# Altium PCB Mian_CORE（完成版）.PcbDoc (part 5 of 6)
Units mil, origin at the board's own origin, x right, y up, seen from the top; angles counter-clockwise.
Board outline 2755.91 x 1771.65 mil, 4 copper layers (TOP, GND02, PWR03, BOTTOM); 61 components, 130 nets, 4907 pads, 497 vias.
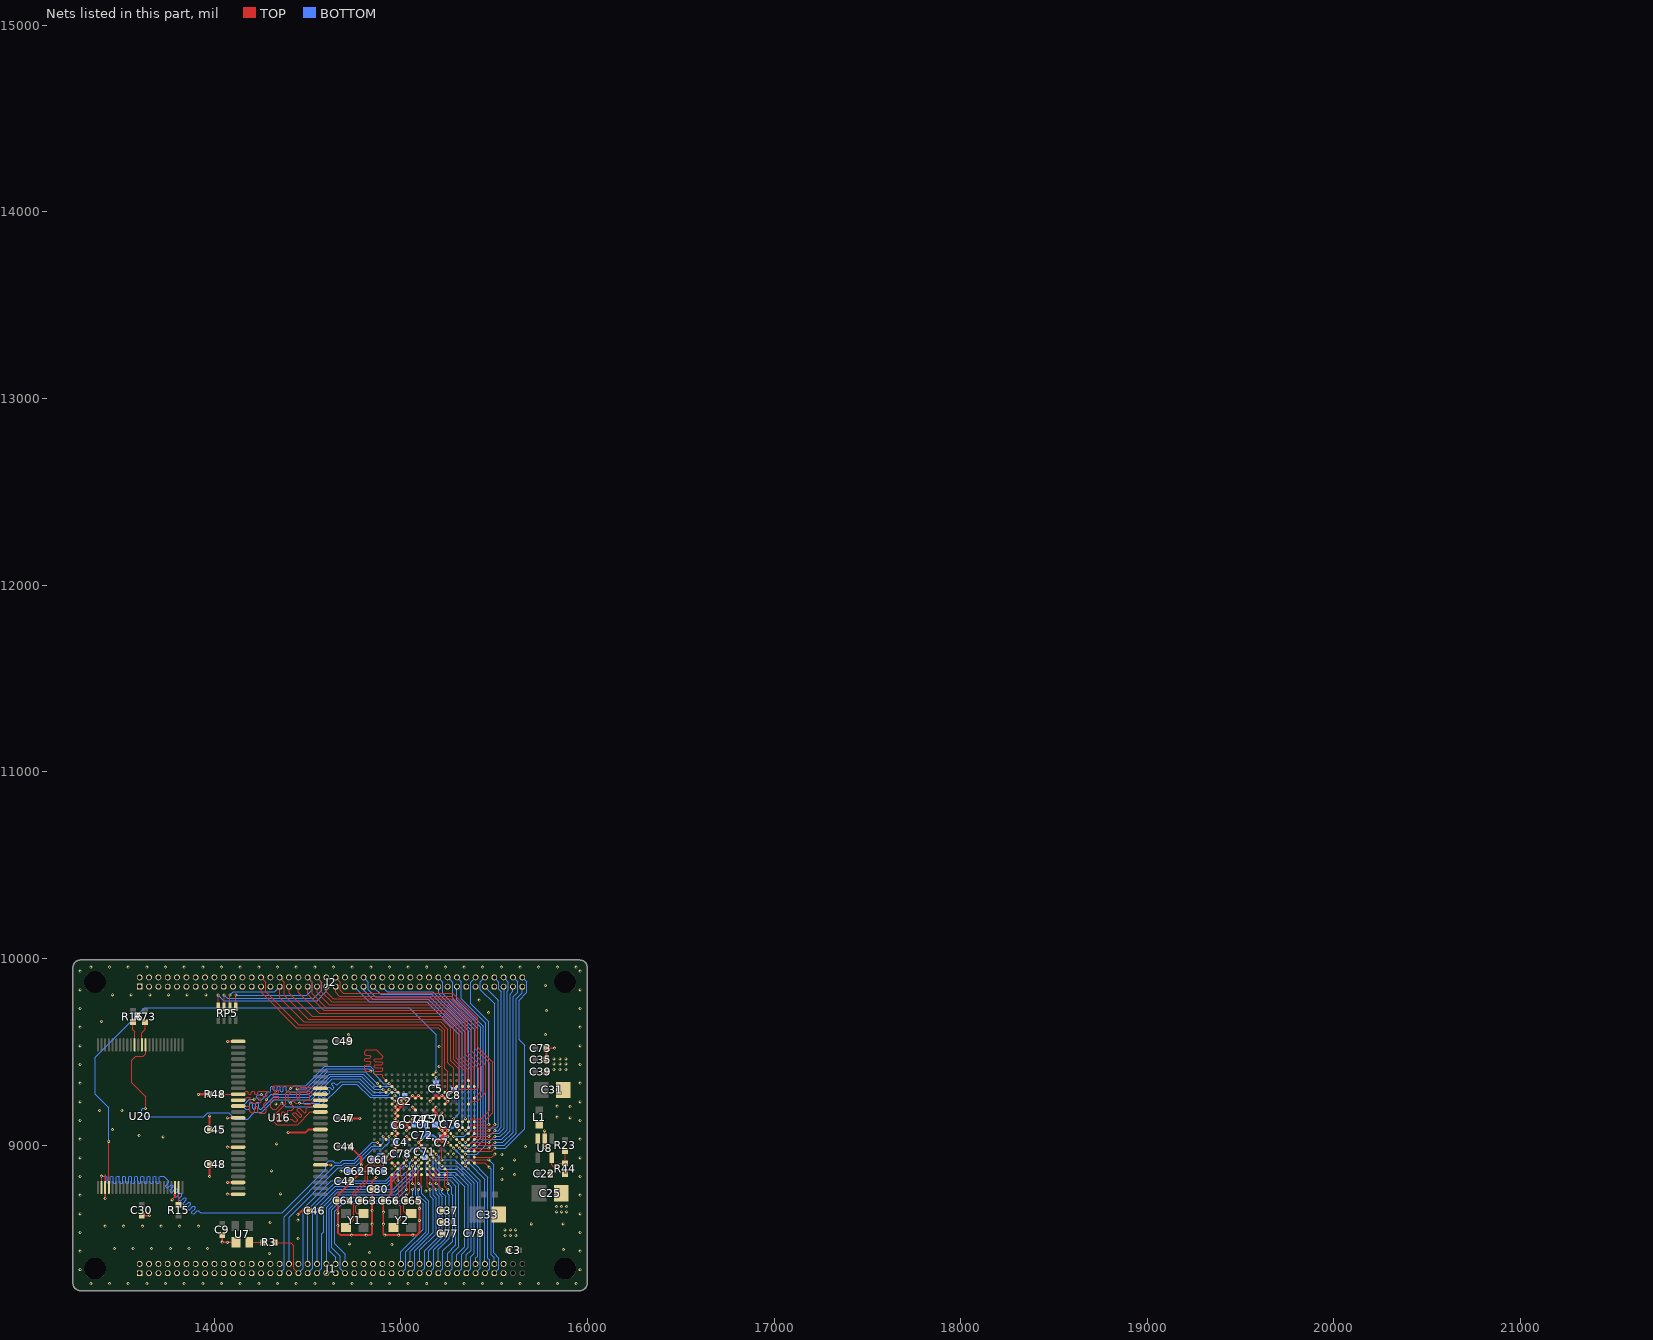
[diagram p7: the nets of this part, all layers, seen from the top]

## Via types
v1: diameter 16, hole 8, TOP to BOTTOM, tented both sides, 497 vias

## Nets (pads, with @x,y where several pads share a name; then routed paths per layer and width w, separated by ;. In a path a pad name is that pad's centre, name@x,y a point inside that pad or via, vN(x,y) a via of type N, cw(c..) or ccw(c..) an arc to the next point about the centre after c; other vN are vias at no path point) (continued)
GND: C2.2 C3.2 C4.2 C5.2 C6.2 C7.2 C8.2 C9.2 C22.1 C25.2 C30.2 C31.2 C33.2 C35.1 C37.1 C39.1 C42.2 C44.2 C45.2 C46.2 C47.2 C48.2 C49.2 C61.2 C62.2 C63.2 C64.2 C65.2 C66.2 C70.2 C71.2 C72.2 C73.2 C74.2 C75.2 C76.2 C77.2 C78.2 C79.2 C80.2 C81.2 J1.1 J1.2 J1.3 J1.4 J1.5 J1.6 J1.7 J1.8 J1.9 J1.10 J1.11 J1.12 J1.13 J1.14 J1.15 J1.16 J1.17 J1.18 J1.19 J1.20 J1.21 J1.22 J1.23 J1.24 J1.25 J1.26 J1.27 J1.28 J1.29 J1.30 J1.32 J1.33 J1.36 J1.41 J1.43 J1.47 J1.48 J1.49 J1.50 J1.51 J1.52 J1.53 J1.54 J1.55 J1.56 J1.79 J1.80 J2.1 J2.2 J2.3 J2.4 J2.5 J2.6 J2.7 J2.8 J2.9 J2.10 J2.11 J2.12 J2.13 J2.14 J2.15 J2.16 J2.17 J2.18 J2.19 J2.20 J2.21 J2.22 J2.23 J2.24 J2.25 J2.26 J2.29 J2.30 J2.34 J2.36 J2.42 J2.45 J2.46 J2.48 J2.52 J2.54 J2.55 J2.56 J2.57 J2.58 J2.59 J2.60 J2.61 J2.62 J2.63 J2.64 J2.67 J2.71 J2.72 J2.73 J2.77 R44.2 R48.1 U1.F5 U1.F6 U1.F10 U1.F11 U1.F12 U1.G5 U1.G8 U1.G10 U1.G12 U1.H5 U1.H7 U1.H12 U1.K5 U1.K12 U1.K13 U1.L5 U1.L7 U1.L14 U1.M5 U1.M9 U1.M10 U1.M12 U1.N5 U1.N6 U1.P6 U1.P7 U1.P8 U1.P9 U1.P10 U1.P11 U1.P13 U1.P14 U1.P18 U1.R16 U1.R18 U1.T15 U7.1 U8.2 U16.6 U16.12 U16.28 U16.41 U16.46 U16.52 U16.54 U20.27 U20.46 | length 5536.5
  TOP w10: v1(13415.99,8714.01) U20.27@13415.99,8773.11 13415.99,8841 ; C30.2@13612,8621.16 v1(13653.84,8621.16) ; v1(13774,8706) 13790.01,8722.01 U20.46@13790.01,8773.11 ; v1(13975.08,8831.08) C48.2@13975.08,8896 ; C45.2@13975.08,9083 v1(13975.08,9155.92) ; C9.2@14043,8517.16 v1(14043,8480) 14044,8479 U7.1@14117.13,8479 ; v1(14072.45,8736.55) U16.54@14128.53,8736.55 ; v1(14072.45,8799.54) U16.52@14128.53,8799.54 ; v1(14072.45,8988.52) U16.46@14128.53,8988.52 ; v1(14072.45,9146) U16.41@14128.53,9146 ; v1(14072.45,9555.45) U16.28@14128.53,9555.45 ; v1(14396,9068) 14489.99,9068 14505,9083.01 U16.12@14569.47,9083.01 ; v1(14448,8627) 14469,8648 C46.2@14510.16,8648 ; U16.6@14569.47,8894.03 v1(14625.55,8894.03) ; 14682.58,8751.58 14698,8767 ; C49.2@14720.92,9555 v1(14720.92,9591.48) ; C47.2@14725.84,9143 v1(14781,9143) ; v1(14788,8892) 14788,8857 14698,8767 ; v1(14867.56,8827) 14846.16,8805.6 C80.2@14846.16,8764 14846,8763.84 C63.2@14846,8701 v1(14846,8648) v1(14846,8576) 14846,8525 14838,8517 v1(14814,8517) v1(14736,8517) 14677,8517 14663.16,8530.84 v1(14663.16,8568) v1(14663.16,8636) C64.2@14663.16,8701 14663.16,8732.16 14698,8767 ; 14949.16,8773 14949.16,8741 C66.2@14909.16,8701 14906,8697.84 v1(14906,8641) v1(14906,8576) 14906,8525 v1(14914,8517) v1(14989,8517) v1(15064,8517) 15085,8517 15100,8532 v1(15100,8596) v1(15100,8659) 15100,8693 C65.2@15092,8701 ; U1.P18@14984.27,8841.28 v1(14984.27,8810.58) v1@14984.38,8810.47 ; v1(15771,8988) U8.2@15771,9034.18 v1(15771,9076) ; C35.1@15779.84,9458 15780.84,9459 C73.2@15780.84,9519 v1(15824,9519)
  TOP w12: v1(13915,9272) R48.1@13975.08,9272 ; C44.2@14728.92,8991 14788,8931.92 v1(14788,8892) ; v1(14905.53,8951.52) U1.T15@14921.28,8935.77 ; 14949.16,8773 14949.16,8837.67 U1.R18@14952.77,8841.28 ; U1.R16@14952.77,8904.28 v1(14968.52,8888.53) ; v1(14968.52,9046.01) U1.P11@14984.27,9061.76 v1(14968.52,9077.5) U1.P10@14984.27,9093.25 14968.52,9109 U1.P9@14984.27,9124.75 v1(14968.52,9140.5) U1.P8@14984.27,9156.24 v1(14968.52,9171.99) U1.P7@14984.27,9187.74 ; U1.P14@14984.27,8967.27 v1(14968.52,8983.02) U1.P13@14984.27,8998.76 ; v1(15031.51,9046.01) U1.M12@15047.26,9030.26 ; v1(15031.51,9077.5) U1.M10@15047.26,9093.25 15031.51,9109 U1.M9@15047.26,9124.75 v1(15063.01,9140.5) ; v1(15063.01,9203.49) U1.L7@15078.76,9187.74 ; U1.L14@15078.76,8967.27 v1(15094.5,8983.02) U1.K13@15110.25,8998.76 v1(15094.5,9014.51) U1.K12@15110.25,9030.26 ; U1.K5@15110.25,9250.73 v1(15094.5,9266.48) U1.L5@15078.76,9250.73 v1(15063.01,9266.48) U1.M5@15047.26,9250.73 v1(15031.51,9234.98) ; v1(15157.5,9234.98) U1.H5@15173.24,9250.73 15188.99,9266.48 U1.G5@15204.74,9250.73 v1(15220.49,9266.48) U1.F5@15236.24,9250.73 ; U1.H12@15173.24,9030.26 v1(15188.99,9014.51) U1.G12@15204.74,9030.26 ; v1(15188.99,9203.49) U1.H7@15173.24,9187.74 15188.99,9171.99 U1.G8@15204.74,9156.24 v1(15220.49,9171.99) ; U1.G10@15204.74,9093.25 v1(15220.49,9077.5) ; U1.F6@15236.24,9219.24 v1(15251.98,9234.98) U1.F5@15236.24,9250.73 ; v1(15251.98,9014.51) U1.F12@15236.24,9030.26 ; v1(15251.98,9266.48) U1.F5@15236.24,9250.73 ; U1.P7@14984.27,9187.74 15000.02,9203.49 ; U1.P7@14984.27,9187.74 v1(14968.52,9203.49) U1.P6@14984.27,9219.24 ; U1.P6@14984.27,9219.24 15000.02,9203.49 ; U1.P6@14984.27,9219.24 v1(15000.02,9234.98) ; 15000.02,9203.49 U1.N6@15015.76,9219.24 ; v1(15000.02,9234.98) U1.N5@15015.76,9250.73 v1(15031.51,9234.98) ; v1(15000.02,9234.98) U1.N6@15015.76,9219.24 ; U1.N6@15015.76,9219.24 v1(15031.51,9234.98) ; U1.G12@15204.74,9030.26 15220.49,9014.51 U1.F12@15236.24,9030.26 ; U1.G12@15204.74,9030.26 15220.49,9046.01 ; 15220.49,9046.01 U1.F12@15236.24,9030.26 ; 15220.49,9046.01 U1.F11@15236.24,9061.76 ; v1(15220.49,9077.5) U1.F11@15236.24,9061.76 ; v1(15220.49,9077.5) U1.F10@15236.24,9093.25 v1(15251.98,9077.5) U1.F11@15236.24,9061.76 ; U1.F12@15236.24,9030.26 v1(15251.98,9046.01) U1.F11@15236.24,9061.76
  BOTTOM w8: v1(15094.5,8983.02) 15122,8955.52
  BOTTOM w10: v1(14679,8860) C62.2@14722.16,8860 ; C61.2@14848.16,8921 14878.68,8951.52 v1(14905.53,8951.52) ; v1(14968.52,9046.01) 14970.16,9044.37 C4.2@14970.16,9015 ; v1(15000.02,9234.98) 15000.02,9243.86 C2.2@15021,9264.84 ; C78.2@15030.84,8953 15060.86,8983.02 v1(15094.5,8983.02) ; v1(15063.01,9140.5) 15063.01,9120.15 C74.2@15074,9109.16 C75.2@15128,9109.16 15133.84,9103.31 15133.84,9052 15175,9052 15188.99,9038.01 v1(15188.99,9014.51) ; C70.2@15183,9110.16 15187.83,9110.16 v1(15220.49,9077.5) ; C5.2@15188,9331 15188.99,9331.99 v1(15188.99,9360.97) ; v1(15251.98,9077.5) 15266.48,9092 15278.84,9092 C76.2@15297.84,9111
  BOTTOM w12: C6.2@14960.08,9106 14960.08,9085.94 v1(14968.52,9077.5) ; v1(15094.5,9014.51) 15096.35,9014.51 C72.2@15133.84,9052 ; 15122,8955.52 15122,8940.16 C71.2@15128,8934.16 ; C7.2@15220.49,9042.86 15223.64,9046.01 v1(15251.98,9046.01) ; v1(15251.98,9266.48) 15281.35,9295.84 C8.2@15285,9295.84
  other v1: 13339,8258 13439,8258 13539,8258 13639,8258 13739,8258 13839,8258 13939,8258 14039,8258 14139,8258 14239,8258 14339,8258 14439,8258 14539,8258 14639,8258 14739,8258 14839,8258 14939,8258 15039,8258 15139,8258 15239,8258 15339,8258 15439,8258 15539,8258 15639,8258 15739,8258 15839,8258 15939,8258 13281,8331.75 15960.91,8331.75 14296,8419 14833,8424 13281,8431.75 15960.91,8431.75 15871,8440 13465,8445 13565,8445 13665,8445 13765,8445 13865,8445 13965,8445 14952,8467 14724,8471 14071,8479 14450,8498 15559,8516 15587.5,8516 15616,8516 13281,8531.75 15960.91,8531.75 15558,8545 15586.5,8545 15615,8545 13415,8566 13515,8566 13615,8566 13715,8566 13815,8566 13915,8566 15699,8577 15870,8577 14300,8585 14449,8598 13281,8631.75 15960.91,8631.75 15835,8642 15861.5,8642 15888,8642 15835,8670 15861.5,8670 15888,8670 13281,8731.75 15960.91,8731.75 14356,8738 15134,8753 15541,8816 13281,8831.75 15960.91,8831.75 15610,8842 14307,8862 15541,8875 15609,8921 13281,8931.75 15960.91,8931.75 15541,8950 15251.98,8951.52 15283.48,8951.52 15668,8992 14334,9006 13281,9031.75 15960.91,9031.75 13726,9044 13598,9051 13454,9082 13281,9131.75 15960.91,9131.75 15907,9145 15838,9150 13386,9186 13505,9186 15907,9206 15838,9208 14330,9221 13281,9231.75 15960.91,9231.75 13281,9331.75 15960.91,9331.75 15820,9406 15852,9406 15884,9406 15205,9421 13281,9431.75 15960.91,9431.75 15820,9435 15852,9435 15884,9435 15820,9462 15852,9462 15884,9462 15205,9527 13281,9531.75 15960.91,9531.75 15775,9592 13281,9631.75 15960.91,9631.75 13397,9663 15471,9709 15780,9720 13281,9731.75 15960.91,9731.75 15420,9776 13455,9805 13555,9805 13655,9805 13755,9805 13855,9805 13955,9805 13281,9831.75 15960.91,9831.75 15775,9855 13281,9931.75 15960.91,9931.75 13339,9953.65 13439,9953.65 13539,9953.65 13639,9953.65 13739,9953.65 13839,9953.65 13939,9953.65 14039,9953.65 14139,9953.65 14239,9953.65 14339,9953.65 14439,9953.65 14539,9953.65 14639,9953.65 14739,9953.65 14839,9953.65 14939,9953.65 15039,9953.65 15139,9953.65 15239,9953.65 15339,9953.65 15439,9953.65 15539,9953.65 15639,9953.65 15739,9953.65 15839,9953.65 15939,9953.65
GPI_00: J1.73 U1.C16 | length 641.8
  TOP w5.5: U1.C16@15330.72,8904.28 v1(15346.47,8888.53)
  BOTTOM w5.5: v1(15346.47,8888.53) 15427,8808 15427,8339.16 J1.73@15400.95,8313.11
GPI_02: J2.70 U1.C14 | length 1114.6
  TOP w5.5: U1.C14@15330.72,8967.27 v1(15346.47,8951.52)
  BOTTOM w5.5: J2.70@15300.95,9898.54 15324,9875.5 15324,9784 15456,9652 15456,9000 15407.52,8951.52 v1(15346.47,8951.52)
GPI_03: J2.28 U1.F4 | length 1479
  TOP w5.5: J2.28@14250.95,9898.54 14276,9873.5 14276,9822 14453.58,9644.42 15207.27,9644.42 15236.42,9615.27 15236.42,9409.58 15252,9394 15252,9297.99 U1.F4@15236.24,9282.23
GPI_04: J1.76 U1.E13 | length 718.7
  TOP w5.5: U1.E13@15267.73,8998.76 v1(15283.48,8983.02)
  BOTTOM w5.5: v1(15283.48,8983.02) 15323,8943.5 15323,8921.02 15339.75,8904.28 15363.72,8904.28 15450.95,8817.05 J1.76@15450.95,8370.05
GPI_05: J1.38 U1.N16 | length 940.8
  TOP w5.5: U1.N16@15015.76,8904.28 v1(15031.51,8888.53)
  BOTTOM w5.5: J1.38@14500.95,8363.11 14500.95,8653.94 14642.01,8795 14924,8795 15017.53,8888.53 v1(15031.51,8888.53)
GPI_07: J2.69 U1.D13 | length 1063.1
  TOP w5.5: U1.D13@15299.23,8998.76 v1(15314.98,8983.02)
  BOTTOM w5.5: J2.69@15300.95,9848.54 15300.95,9779.05 15443,9637 15443,9025 15385.27,8967.27 15330.72,8967.27 v1(15314.98,8983.02)
GPI_08: J1.77 U1.B16 | length 747.9
  TOP w5.5: U1.B16@15362.22,8904.28 15377.97,8920.02 v1(15472.46,8920.02)
  BOTTOM w5.5: v1(15472.46,8920.02) 15498,8894.48 15498,8422 15526,8394 15526,8338.16 J1.77@15506.84,8319
GPI_16: J1.59 U1.J18 | length 591.5
  TOP w5.5: U1.J18@15141.75,8841.28 15141.75,8778.29 v1(15157.5,8762.54)
  BOTTOM w5.5: J1.59@15050.95,8313.11 15075,8337.16 15075,8434 15172.75,8531.75 15172.75,8709.25 15157.5,8724.5 v1(15157.5,8762.54)
GPI_22: J1.74 U1.G13 | length 765.4
  TOP w5.5: U1.G13@15204.74,8998.76 15220.49,8983.02 v1(15220.49,8920.02)
  BOTTOM w5.5: v1(15220.49,8920.02) 15288.98,8920.02 15411,8798 15411,8405 15400.95,8394.95 J1.74@15400.95,8363.11
GPIO_00: J2.80 U1.A12 | length 1027.2
  TOP w5.5: U1.A12@15393.72,9030.26 15488.21,9030.26 v1(15503.95,9046.01)
  BOTTOM w5.5: v1(15503.95,9046.01) 15534.18,9046.01 15570.5,9082.33 15570.5,9823.5 15576,9829 15576,9873.5 J2.80@15550.95,9898.54
GPIO_01: J2.78 U1.A11 | length 978.1
  TOP w5.5: U1.A11@15393.72,9061.76 15488.21,9061.76 v1(15503.95,9077.5)
  BOTTOM w5.5: J2.78@15500.95,9898.54 15526,9873.5 15526,9834 15539,9821 15539,9095.37 15521.13,9077.5 v1(15503.95,9077.5)
GPO_00: J2.33 U1.C3 | length 1456.7
  TOP w5.5: J2.33@14400.95,9848.54 14400.95,9814.05 14524.33,9690.67 15226.43,9690.67 15282.67,9634.43 15282.67,9586 ; 15282.67,9474 15282.67,9586 ; U1.C3@15330.72,9313.72 15347,9330 15347,9394 15282.67,9458.33 15282.67,9586
GPO_01: J2.39 U1.D4 | length 1400.1
  TOP w5.5: J2.39@14550.95,9848.54 14550.95,9817.05 14615.67,9752.33 15251.97,9752.33 15344.33,9659.97 15344.33,9638.41 15344.33,9486.19 15418,9412.53 15418,9311 15405,9298 15315,9298 U1.D4@15299.23,9282.23
GPO_02: J2.83 U1.B14 | length 1087.9
  TOP w5.5: U1.B14@15362.22,8967.27 15377.97,8983.02 v1(15472.46,8983.02)
  BOTTOM w5.5: v1(15472.46,8983.02) 15488.46,8999.02 15553.64,8999.02 15617.49,9062.86 15617.49,9783.49 15650.95,9816.95 J2.83@15650.95,9842.05
GPO_03: J2.66 U1.D12 | length 1084.8
  TOP w5.5: U1.D12@15299.23,9030.26 v1(15314.98,9014.51)
  BOTTOM w5.5: J2.66@15200.95,9898.54 15226,9873.5 15226,9810 15412,9624 15412,9047 15363.76,8998.76 15330.72,8998.76 v1(15314.98,9014.51)
GPO_05: J2.37 U1.B3 | length 1288.6
  TOP w5.5: J2.37@14500.95,9848.54 14500.95,9807.05 14586.5,9721.5 15239.2,9721.5 15313.5,9647.2 15313.5,9470.5 15380,9404 15380,9331.5 U1.B3@15362.22,9313.72
GPO_06: J1.78 U1.A16 | length 619
  TOP w5.5: U1.A16@15393.72,8904.28 15450.72,8904.28 v1(15473,8882)
  BOTTOM w5.5: v1(15473,8882) 15485,8870 15485,8411 15500.95,8395.05 J1.78@15500.95,8363.11
GPO_07: U1.A15 | length 116.8
  TOP w5.5: U1.A15@15393.72,8935.77 15488.21,8935.77 v1(15503.95,8951.52)
GPO_08: J2.68 U1.C13 | length 1061.3
  TOP w5.5: U1.C13@15330.72,8998.76 v1(15346.47,8983.02)
  BOTTOM w5.5: J2.68@15250.95,9898.54 15277,9872.5 15277,9782 15429,9630 15429,9039 15373.02,8983.02 v1(15346.47,8983.02)
GPO_09: J2.65 U1.C12 | length 959
  TOP w5.5: U1.C12@15330.72,9030.26 v1(15346.47,9014.51)
  BOTTOM w5.5: J2.65@15204,9852 15204,9810 15395,9619 15395,9063.04 v1(15346.47,9014.51)
GPO_10: J2.53 U1.E11 | length 1237.9
  TOP w5.5: U1.E11@15267.73,9061.76 v1(15283.48,9046.01)
  BOTTOM w5.5: J2.53@14900.95,9848.54 14927.5,9822 15171,9822 15378,9615 15378,9083 15341.01,9046.01 v1(15283.48,9046.01)
GPO_12: J2.79 U1.B12 | length 977.6
  TOP w5.5: U1.B12@15362.22,9030.26 15377.97,9046.01 v1(15472.46,9046.01)
  BOTTOM w5.5: v1(15472.46,9046.01) 15488.46,9062.01 15527.55,9062.01 15554.5,9088.95 15554.5,9695 15554.5,9845 J2.79@15550.95,9848.54
GPO_13: J2.81 U1.B13 | length 1034.6
  TOP w5.5: U1.B13@15362.22,8998.76 15377.97,9014.51 v1(15472.46,9014.51)
  BOTTOM w5.5: v1(15472.46,9014.51) 15488.46,9030.51 15540.6,9030.51 15585.99,9075.91 15585.99,9808.99 15600.95,9823.95 J2.81@15600.95,9848.54
GPO_14: J2.32 U1.D3 | length 1501.3
  TOP w5.5: J2.32@14350.95,9898.54 14376,9873.5 14376,9803 14503.75,9675.25 15220.04,9675.25 15267.25,9628.04 15267.25,9565 ; 15267.25,9474 15267.25,9565 ; U1.D3@15299.23,9313.72 15315,9329.5 15315,9403 15267.25,9450.75 15267.25,9565
GPO_15: J2.84 U1.A14 | length 1171.5
  TOP w5.5: U1.A14@15393.72,8967.27 15488.21,8967.27 v1(15503.95,8983.02)
  BOTTOM w5.5: v1(15503.95,8983.02) 15560.27,8983.02 15664,9086.75 15664,9534 15634,9564 15634,9777 15675.71,9818.71 15675.71,9873.78 J2.84@15650.95,9898.54
GPO_16: J2.49 U1.D10 | length 1191.8
  TOP w5.5: U1.D10@15299.23,9093.25 v1(15314.98,9077.5)
  BOTTOM w5.5: J2.49@14800.95,9848.54 14800.95,9830.05 14850,9781 15147,9781 15329,9599 15329,9091.53 v1(15314.98,9077.5)
GPO_20: J2.35 U1.B2 | length 1388.2
  TOP w5.5: J2.35@14450.95,9848.54 14450.95,9818.05 14562.92,9706.08 15232.81,9706.08 15298.08,9640.81 15298.08,9589 ; 15298.08,9474 15298.08,9589 ; U1.B2@15362.22,9345.22 15362.22,9399.78 15298.08,9463.92 15298.08,9589
LDQM0: U1.R3 U16.15 | length 1150.6
  TOP w5.5: v1(14408.46,9302) 14384,9277.54 14384,9222 14317,9155 14317,9128 14336,9109 14447,9109 14515.5,9177.5 U16.15@14569.47,9177.5 ; v1(14937.02,9329.47) U1.R3@14952.77,9313.72
  BOTTOM w5.5: v1(14408.46,9302) 14425.46,9319 14490,9319 14593,9422 14836,9422 14854.99,9403.01 14854.99,9384.01 14909.53,9329.47 v1(14937.02,9329.47)
LDQM1: U1.P4 U16.39 | length 1118.2
  TOP w5.5: U16.39@14128.53,9208.99 14185.01,9208.99 14191,9203 14191,9181 14198,9174 14209,9174 14217.25,9182.25 14217.25,9203.05 14222.2,9208 14228.8,9208 14233.75,9203.05 14233.75,9179.25 14243,9170 14272,9170 14280,9178 14280,9192 14265,9207 14265,9218 14280,9233 v1(14280,9245) ; v1(14968.52,9297.98) U1.P4@14984.27,9282.23
  BOTTOM w5.5: v1(14280,9245) 14306,9271 14507,9271 14616,9380 14798,9380 14864,9314 14952.5,9314 v1(14968.52,9297.98)
LNSDCAS: U1.R5 U16.17 | length 1297.5
  TOP w5.5: v1(14457,9224) 14437,9224 14417,9244 14402,9244 14398,9248 14398,9268 14412,9282 14438.3,9282 14443.25,9277.05 14443.25,9252.95 14448.2,9248 14454.8,9248 14459.75,9252.95 14459.75,9277.05 14464.7,9282 14494,9282 14511.5,9264.5 14511.5,9245.5 14505,9239 14487,9239 14481,9233 14481,9222 14484,9219 14515,9219 14536.49,9240.49 U16.17@14569.47,9240.49 ; U1.R5@14952.77,9250.73 v1(14968.52,9266.48)
  BOTTOM w5.5: v1(14457,9224) 14562,9224 14571.45,9233.45 14571.45,9240.45 14559.62,9252.28 14559.62,9259.28 14564.29,9263.95 14571.29,9263.95 14583.12,9252.12 14590.12,9252.12 14594.79,9256.79 14594.79,9263.79 14582.96,9275.62 14582.96,9282.62 14587.63,9287.28 14594.63,9287.28 14606.45,9275.46 14613.45,9275.45 14618.12,9280.12 14618.12,9287.12 14606.29,9298.95 14606.29,9305.95 14610.96,9310.62 14617.96,9310.62 14629.79,9298.79 14636.79,9298.79 14641.46,9303.46 14641.46,9310.46 14629.63,9322.29 14629.63,9329.29 14634.3,9333.95 14641.3,9333.95 14653.12,9322.12 14660.12,9322.12 14678,9340 14774,9340 14847.52,9266.48 14931,9266.48 14946.75,9282.23 14988.21,9282.23 14993.44,9277 14993.44,9259.91 14988.54,9255 14980,9255 v1(14968.52,9266.48)
LNSDCS0: U1.R6 U16.19 | length 1292.5
  TOP w5.5: v1(14363,9224) 14332,9193 14314,9193 14304,9203 14304,9231.3 14317.95,9245.25 14342.05,9245.25 14347,9250.2 14347,9256.8 14342.05,9261.75 14317.95,9261.75 14313,9266.7 14313,9273.3 14317.95,9278.25 14342.05,9278.25 14347,9283.2 14347,9289.8 14342.05,9294.75 14317.95,9294.75 14313,9299.7 14313,9312 14320,9319 14453,9319 14462,9310 14519.48,9310 14526,9303.48 U16.19@14569.47,9303.48 ; U1.R6@14952.77,9219.24 v1(14968.52,9234.98)
  BOTTOM w5.5: v1(14363,9224) 14383,9204 14565,9204 14688,9327 14764,9327 14836,9255 14948.5,9255 v1(14968.52,9234.98)
LNSDRAS: U1.T2 U16.18 | length 1300
  TOP w5.5: v1(14445,9301) 14449,9297 14502,9297 14527.02,9271.98 U16.18@14569.47,9271.98 ; v1(14838.97,9396.03) 14812.97,9396.03 14806,9403 14806,9426.3 14810.95,9431.25 14832.76,9431.25 14837.71,9436.2 14837.71,9442.8 14832.76,9447.75 14810.95,9447.75 14806,9452.7 14806,9459.3 14810.95,9464.25 14832.76,9464.25 14837.71,9469.2 14837.71,9475.8 14832.76,9480.75 14810.95,9480.75 14806,9485.7 14806,9501 14816,9511 14868,9511 14902,9477 14902,9467.7 14897.05,9462.75 14862.95,9462.75 14858,9457.8 14858,9451.2 14862.95,9446.25 14897.05,9446.25 14902,9441.3 14902,9434.7 14897.05,9429.75 14862.95,9429.75 14858,9424.8 14858,9418.2 14862.95,9413.25 14897.05,9413.25 14902,9408.3 14902,9401.7 14897.05,9396.75 14862.95,9396.75 14858,9391.8 14858,9385.2 14862.95,9380.25 14897.05,9380.25 14902,9375.3 14902,9364.5 U1.T2@14921.28,9345.22
  BOTTOM w5.5: v1(14445,9301) 14494,9301 14600.47,9407.47 14827.53,9407.47 v1(14838.97,9396.03)
MISO0: J2.51 U1.C10 | length 1173.3
  TOP w5.5: U1.C10@15330.72,9093.25 v1(15346.47,9077.5)
  BOTTOM w5.5: J2.51@14850.95,9848.54 14891.5,9808 15165,9808 15364,9609 15364,9095.03 v1(15346.47,9077.5)
MISO1: J2.76 U1.A10 | length 948.1
  TOP w5.5: U1.A10@15393.72,9093.25 15488.21,9093.25 v1(15503.95,9109)
  BOTTOM w5.5: J2.76@15450.95,9898.54 15427,9874.59 15427,9833 15503.95,9756.05 v1(15503.95,9109)
MOSI0: J2.43 U1.B9 | length 1515.7
  TOP w5.5: J2.43@14650.95,9848.54 14650.95,9818.05 14670.42,9798.58 14697,9798.58 ; 14678,9798.58 14697,9798.58 ; U1.B9@15362.22,9124.75 15377.97,9140.5 15431.5,9140.5 15477,9186 15477,9437.79 15398,9516.79 15398,9671.71 15271.13,9798.58 14697,9798.58
MOSI1: J2.44 U1.A9 | length 1535.8
  TOP w5.5: J2.44@14650.95,9898.54 14676,9873.5 14676,9829 14691,9814 15277.51,9814 15413,9678.51 15413,9523 15492,9444 15492,9173 15443.75,9124.75 U1.A9@15393.72,9124.75
NCS0: U1.U13 U20.26 | length 2835.4
  TOP w5.5: v1(13396,8834) 13396.31,8833.69 U20.26@13396.31,8773.11 U20.26@13397,8772.42 ; v1(14874.03,9014.51) U1.U13@14889.78,8998.76
  BOTTOM w5.5: v1(13396,8834) 13408,8834 13409.75,8834 13421.3,8834 13426.25,8829.05 13426.25,8798.95 13431.2,8794 13437.8,8794 13442.75,8798.95 13442.75,8829.05 13447.7,8834 13454.3,8834 13459.25,8829.05 13459.25,8798.95 13464.2,8794 13470.8,8794 13475.75,8798.95 13475.75,8829.05 13480.7,8834 13487.3,8834 13492.25,8829.05 13492.25,8798.95 13497.2,8794 13503.8,8794 13508.75,8798.95 13508.75,8829.05 13513.7,8834 13520.3,8834 13525.25,8829.05 13525.25,8798.95 13530.2,8794 13536.8,8794 13541.75,8798.95 13541.75,8829.05 13546.7,8834 13553.3,8834 13558.25,8829.05 13558.25,8798.95 13563.2,8794 13569.8,8794 13574.75,8798.95 13574.75,8829.05 13579.7,8834 13586.3,8834 13591.25,8829.05 13591.25,8798.95 13596.2,8794 13602.8,8794 13607.75,8798.95 13607.75,8829.05 13612.7,8834 13619.3,8834 13624.25,8829.05 13624.25,8798.95 13629.2,8794 13635.8,8794 13640.75,8798.95 13640.75,8829.05 13645.7,8834 13652.3,8834 13657.25,8829.05 13657.25,8798.95 13662.2,8794 13668.8,8794 13673.75,8798.95 13673.75,8829.05 13678.7,8834 13685.3,8834 13690.25,8829.05 13690.25,8798.95 13695.2,8794 13701.8,8794 13706.75,8798.95 13706.75,8829.05 13711.7,8834 13715,8834 13730,8834 13757,8807 13757.4,8806.6 13757.4,8799.6 13740.36,8782.56 13740.36,8775.56 13745.02,8770.89 13752.02,8770.89 13769.06,8787.93 13776.07,8787.93 13780.73,8783.27 13780.73,8776.27 13763.69,8759.23 13763.69,8752.23 13768.36,8747.56 13775.36,8747.56 13792.4,8764.6 13799.4,8764.6 13804.07,8759.93 13804.07,8752.93 13787.03,8735.89 13787.03,8728.89 13791.69,8724.22 13798.69,8724.22 13815.73,8741.27 13822.73,8741.27 13827.4,8736.6 13827.4,8729.6 13810.36,8712.56 13810.36,8705.56 13815.03,8700.89 13822.03,8700.89 13839.07,8717.93 13846.07,8717.93 13850.74,8713.26 13850.74,8706.26 13833.69,8689.22 13833.69,8682.22 13838.36,8677.56 13845.36,8677.56 13862.4,8694.6 13869.4,8694.6 13874.07,8689.93 13874.07,8682.93 13857.03,8665.89 13857.03,8658.89 13861.7,8654.22 13868.7,8654.22 13885.74,8671.26 13892.74,8671.26 13897.4,8666.6 13897.4,8659.6 13880.36,8642.55 13880.36,8635.55 13885.03,8630.89 13892.03,8630.89 13909.07,8647.93 13916.07,8647.93 13918.41,8645.59 13927,8637 14365,8637 14599,8871 14599,8899 14615,8915 14635,8915 14645,8905 14676,8905 14690,8919 14751,8919 14846.51,9014.51 v1(14874.03,9014.51)
NCS1: J1.34 U1.R11 | length 1006.3
  TOP w5.5: v1(14937.02,9046.01) U1.R11@14952.77,9061.76
  BOTTOM w5.5: J1.34@14400.95,8363.11 14400.95,8613.95 14665.03,8878.03 14691.03,8878.03 14701,8888 14760,8888 14851,8979 14901,8979 14937.02,9015.02 v1(14937.02,9046.01)
NCS2: J1.31 U1.T12 | length 1064.9
  TOP w5.5: v1(14905.53,9046.01) U1.T12@14921.28,9030.26
  BOTTOM w5.5: J1.31@14350.95,8313.11 14375,8337.16 14375,8617 14648.47,8890.47 14684.47,8890.47 14697,8903 14754,8903 14844,8993 14887.53,8993 14905.53,9011 v1(14905.53,9046.01)
NetC61_1: C61.1 R63.1 U1.R14 | length 125.8
  TOP w5.5: v1(14937.02,8951.52) U1.R14@14952.77,8967.27
  BOTTOM w5.5: R63.1@14908,8860 C61.1@14908,8921 14937.02,8950.02 v1(14937.02,8951.52)
NetC62_1: C62.1 R63.2 | length 66.2
  BOTTOM w5.5: C62.1@14782,8860 R63.2@14848.16,8860
NetC63_1: C63.1 U1.T17 Y1.2 | length 439.8
  TOP w5.5: Y1.2@14800.24,8633.4 14764.6,8633.4 14758,8640 14758,8672.84 C63.1@14786.16,8701 14758,8729.16 14758,8742.62 14822,8806.62 14822,8872 14838.65,8888.65 14904.71,8888.65 14905.05,8889 U1.T17@14921.28,8872.78
NetC64_1: C64.1 U1.R15 Y1.1 | length 551.5
  TOP w5.5: Y1.1@14705.76,8558.6 14747,8599.84 14747,8677 C64.1@14723,8701 14745,8723 14745,8748 14809,8812 14809,8881 14848.02,8920.02 14937.02,8920.02 U1.R15@14952.77,8935.77
NetC65_1: C65.1 U1.P16 Y2.2 | length 361.9
  TOP w5.5: U1.P16@14984.27,8904.28 15000,8888.54 15000,8832 15007,8825 15007,8725 15031,8701 C65.1@15032.16,8701 ; Y2.2@15032.16,8646.84 15045.6,8633.4 Y2.2@15055.18,8633.4 15025.6,8633.4 15015,8644 15015,8683.84 C65.1@15032.16,8701 ; C65.1@15032.16,8701.84 C65.1@15032.16,8701
NetC66_1: C66.1 U1.P17 Y2.1 | length 370.3
  TOP w5.5: Y2.1@14960.69,8558.6 15001,8598.91 15001,8669 C66.1@14969,8701 14989,8721 14989,8779 14965,8803 14965,8825.48 14968.52,8829 14968.52,8857.03 U1.P17@14984.27,8872.78
NetL1_1: L1.1 U8.3
NetR3_1: R3.1 U7.2 | length 75
  TOP w5.5: U7.2@14189,8478 R3.1@14264,8478
NetR15_2: R15.2 U20.47 | length 91.4
  TOP w5.5: R15.2@13809,8681 U20.47@13809,8772.42
NetR16_2: R16.2 U20.14 | length 125.3
  TOP w5.5: R16.2@13564,9658.31 13564,9619 13573.47,9609.53 U20.14@13573.47,9536.89
NetR23_2: R23.2 R44.1 U8.5 | length 195.2
  TOP w5.5: U8.5@15808.4,8931.82 15808.4,8894.6 15818,8885 15833,8885 15850.84,8902.84 R44.1@15880,8902.84 R23.2@15880,8968 R23.2@15873,8975
NetR73_2: R73.2 U20.12 | length 128.5
  TOP w5.5: U20.12@13612.84,9536.89 13612.84,9602.84 13630,9620 R73.2@13630,9658.31
NOE: U1.H1 U20.28 | length 2943.2
  TOP w5.5: v1(13435,9019) 13435.68,9018.32 U20.28@13435.68,8773.11 ; U1.H1@15173.24,9376.72 v1(15188.99,9392.46)
  BOTTOM w5.5: v1(13435,9019) 13435,9201 13363,9273 13363,9471 13627,9735 15044,9735 15188.99,9590.01 v1(15188.99,9392.46)
NRESET: J1.35 R3.2 U1.M14 | length 1339.1
  TOP w5.5: R3.2@14323.84,8478 14325.05,8476.8 14409,8476.8 14426,8459.8 14426,8338.06 J1.35@14450.95,8313.11 ; v1(15031.51,8920.02) 15031.51,8951.52 U1.M14@15047.26,8967.27
  BOTTOM w5.5: J1.35@14456.84,8319 14477,8339.16 14477,8659 14627,8809 14920.49,8809 v1(15031.51,8920.02) 15031.51,8924.51 v1@15029.27,8922.27
NSYSRESET: J2.27 U1.G4 | length 1420
  TOP w5.5: J2.27@14250.95,9848.54 14250.95,9819.05 14441,9629 15200.88,9629 15221,9608.88 15221,9298.49 U1.G4@15204.74,9282.23
NTRST: J1.64 U1.H17 | length 549.2
  TOP w5.5: U1.H17@15173.24,8872.78 15188.99,8857.03 v1(15188.99,8794.04)
  BOTTOM w5.5: J1.64@15150.95,8374.05 15150.95,8433.95 15223,8506 15223,8723 15205,8741 15205,8778.03 v1(15188.99,8794.04)
NWE: U1.R4 U16.16 U20.11 | length 2654.8
  TOP w5.5: v1@13632.53,9198.53 13632.53,9259.47 13559,9333 13559,9455 13580,9476 13620.53,9476 13632.53,9488 U20.11@13632.53,9536.89 ; v1(14408.46,9224) 14426,9206.46 14426,9197 14416,9187 14399,9187 14395,9183 14395,9158 14392,9155 14382,9155 14378,9159 14378,9174 14374,9178 14367,9178 14362,9173 14362,9162 14355,9155 14344,9155 14334,9145 14334,9130 14340,9124 14348,9124 14358,9134 14369,9134 14379,9124 14392,9124 14407,9139 14415,9139 14430,9124 14440,9124 14446.24,9130.24 14446.24,9137.24 14422.13,9161.35 14422.13,9168.35 14426.79,9173.02 14433.79,9173.02 14457.91,9148.91 14464.91,9148.91 14469.57,9153.57 14469.57,9160.57 14445.46,9184.69 14445.46,9191.69 14450.13,9196.35 14457.13,9196.35 14481.24,9172.24 14488.24,9172.24 14494,9178 14494,9195 14501,9202 14518,9202 14524.99,9208.99 U16.16@14569.47,9208.99 ; v1(14937.02,9297.98) U1.R4@14952.77,9282.23
  BOTTOM w5.5: v1(13631,9197) 13617,9197 13611,9191 13611,9168 13628,9151 13944,9151 13965,9172 14077,9172 14110,9139 14179,9139 14215.2,9175.2 14255.2,9175.2 14322,9242 14390.46,9242 v1(14408.46,9224) 14426.46,9242 14520,9242 14632,9354 14780,9354 14851.77,9282.23 14921.28,9282.23 v1(14937.02,9297.98)
P0.2: J1.44 U1.M17 | length 903.1
  TOP w5.5: v1(15031.51,8762.54) 15031.51,8813 ; 15031.51,8794.04 15031.51,8813 ; U1.M17@15047.26,8872.78 15031.51,8857.03 15031.51,8813
  BOTTOM w5.5: J1.44@14650.95,8363.11 14650.95,8399.05 14617,8433 14617,8659 14677,8719 14987.97,8719 v1(15031.51,8762.54)
P0.3: J1.45 U1.M18 | length 951.1
  TOP w5.5: v1(15031.51,8731.05) 15047.26,8746.79 U1.M18@15047.26,8841.28
  BOTTOM w5.5: 14631,8467 14631,8499 ; J1.45@14700.95,8313.11 14676,8338.06 14676,8404 14631,8449 14631,8499 ; v1(15031.51,8731.05) 15002.65,8702.19 14679.19,8702.19 14631,8654 14631,8499
P0.4: J1.37 U1.L15 | length 1040.7
  TOP w5.5: v1(15063.01,8920.02) U1.L15@15078.76,8935.77
  BOTTOM w5.5: J1.37@14500.95,8313.11 14527,8339.16 14527,8658.09 14647.91,8779 14928,8779 14986,8837 15010.91,8837 15047,8873.09 15047,8904.02 v1(15063.01,8920.02)
P0.5: J1.40 U1.L16 | length 925.6
  TOP w5.5: v1(15063.01,8888.53) U1.L16@15078.76,8904.28
  BOTTOM w5.5: J1.40@14550.95,8375.95 14550.95,8659.4 14655.55,8764 14960.55,8764 15063.01,8866.46 v1(15063.01,8888.53)
P0.6: J1.46 U1.L18 | length 879.6
  TOP w5.5: v1(15063.01,8762.54) 15078.76,8778.29 U1.L18@15078.76,8841.28
  BOTTOM w5.5: J1.46@14700.95,8363.11 14700.95,8414.05 14645,8470 14645,8645 14688.19,8688.19 15027.19,8688.19 15063.01,8724.01 v1(15063.01,8762.54)
P0.7: J1.58 U1.L17 | length 584.2
  TOP w5.5: v1(15063.01,8794.04) 15063.01,8857.03 U1.L17@15078.76,8872.78
  BOTTOM w5.5: J1.58@15000.95,8368.05 15000.95,8428.95 15120,8548 15120,8683.75 15079,8724.75 15079,8778.05 v1(15063.01,8794.04)
RTCK: J1.61 U1.H18 | length 570.2
  TOP w5.5: U1.H18@15173.24,8841.28 15173.24,8778.29 v1(15188.99,8762.54)
  BOTTOM w5.5: J1.61@15110.84,8323 15127,8339.16 15127,8434 15204.75,8511.75 15204.75,8722.25 15188.99,8738.01 v1(15188.99,8762.54)
SCK0: J2.50 U1.C9 | length 1177.3
  TOP w5.5: U1.C9@15330.72,9124.75 v1(15346.47,9140.5)
  BOTTOM w5.5: J2.50@14800.95,9898.54 14826,9873.5 14826,9832 14864,9794 15156,9794 15346.47,9603.53 v1(15346.47,9140.5)
SCK1: J2.74 U1.B10 | length 957.4
  TOP w5.5: U1.B10@15362.22,9093.25 15377.97,9109 v1(15472.46,9109)
  BOTTOM w5.5: J2.74@15400.95,9898.54 15375,9872.59 15375,9758 15472.46,9660.54 v1(15472.46,9109)
SCL1: J2.40 RP5.3 U1.A5 | length 2089.4
  TOP w5.5: RP5.3@14053.01,9741 v1(14053.01,9804) ; J2.40@14550.95,9898.54 14575,9874.5 14575,9822 14629.25,9767.75 15258.35,9767.75 15360,9666.1 15360,9494.57 15435,9419.57 15435,9292.02 U1.A5@15393.72,9250.73
  BOTTOM w5.5: v1(14053.01,9804) 14070.01,9787 14533,9787 14576,9830 14576,9873.5 J2.40@14550.95,9898.54
SCL2: J2.38 RP5.1 U1.A3 | length 1886.7
  TOP w5.5: RP5.1@14116,9741 v1(14116,9804) ; J2.38@14505.5,9894 14526,9873.5 14526,9812 14601.08,9736.92 15245.58,9736.92 15328.92,9653.58 15328.92,9476.08 15393.72,9411.28 U1.A3@15393.72,9313.72
  BOTTOM w5.5: v1(14116,9804) 14497,9804 14526,9833 14526,9873.5 J2.38@14500.95,9898.54
SDA1: J2.41 RP5.4 U1.B6 | length 2107.2
  TOP w5.5: RP5.4@14021.51,9741 v1(14021.51,9804) ; J2.41@14600.95,9848.54 14600.95,9821.21 14639,9783.17 15264.74,9783.17 15381,9666.91 15381,9503.27 15456,9428.27 15456,9282 15409,9235 15377.98,9235 U1.B6@15362.22,9219.24
  BOTTOM w5.5: v1(14021.51,9804) 14051.51,9774 14551,9774 14600.95,9823.95 J2.41@14600.95,9848.54
SDA2: J2.31 RP5.2 U1.E4 | length 1752.9
  TOP w5.5: RP5.2@14084.5,9741 v1(14084.5,9804) ; J2.31@14350.95,9848.54 14350.95,9788.05 14479.17,9659.83 15213.65,9659.83 15251.83,9621.65 15251.83,9490 ; 15251.83,9474 15251.83,9490 ; U1.E4@15267.73,9282.23 15283,9297.5 15283,9411 15251.83,9442.17 15251.83,9490
  BOTTOM w5.5: v1(14084.5,9804) 14102.5,9822 14324.41,9822 J2.31@14350.95,9848.54
SDR_CKE0: R48.2 U1.U3 U16.37 | length 1300
  TOP w5.5: R48.2@14034.92,9272 U16.37@14128.53,9271.98 14153.98,9271.98 14169,9287 14178.3,9287 14183.25,9282.05 14183.25,9275.95 14188.2,9271 14194.8,9271 14199.75,9275.95 14199.75,9282.05 14204.7,9287 14211.3,9287 14216.25,9282.05 14216.25,9275.95 14221.2,9271 14227.8,9271 14232.75,9275.95 14232.75,9282.05 14237.7,9287 14279,9287 14285,9281 14285,9267 14280,9262 14263,9262 v1@14253.02,9271.98 ; v1(14874.03,9329.47) U1.U3@14889.78,9313.72
  BOTTOM w5.5: v1(14253,9270) 14235,9270 14229,9264 14229,9253 14238,9244 14255,9244 14276,9265 14276,9276 14285,9285 14299.3,9285 14304.25,9289.95 14304.25,9310.05 14309.2,9315 14315.8,9315 14320.75,9310.05 14320.75,9289.95 14325.7,9285 14332.3,9285 14337.25,9289.95 14337.25,9310.05 14342.2,9315 14348.8,9315 14353.75,9310.05 14353.75,9289.95 14358.7,9285 14365.3,9285 14370.25,9289.95 14370.25,9310.05 14375.2,9315 14381.8,9315 14386.75,9310.05 14386.75,9289.95 14391.7,9285 14498,9285 14606,9393 14810.5,9393 v1(14874.03,9329.47)
SDR_CLK: U1.T4 U16.38 | length 1300
  TOP w5.5: U16.38@14128.53,9240.49 14157.49,9240.49 14174,9257 14187,9257 14192,9252 14192,9228 14197,9223 14242,9223 14251,9232 14251,9248 14245,9254 14223.54,9254 v1(14214.54,9245) ; v1(14905.53,9297.98) U1.T4@14921.28,9282.23
  BOTTOM w5.5: v1(14214.54,9245) 14189,9245 14161,9217 14161,9200 14169,9192 14185.3,9192 14190.25,9196.95 14190.25,9223.97 14195.2,9228.92 14201.8,9228.92 14206.75,9223.97 14206.75,9196.95 14211.7,9192 14218.3,9192 14223.25,9196.95 14223.25,9224.97 14228.2,9229.92 14234.8,9229.92 14239.75,9224.97 14239.75,9196.95 14244.7,9192 14252,9192 14317,9257 14513,9257 14623.41,9367.41 14788.59,9367.41 14858.02,9297.98 v1(14905.53,9297.98)
SERVICES_N: J1.75 U1.C15 | length 709.3
  TOP w5.5: U1.C15@15330.72,8935.77 v1(15346.47,8920.02)
  BOTTOM w5.5: v1(15346.47,8920.02) 15373.98,8920.02 15467,8827 15467,8394 15476,8385 15476,8338.16 J1.75@15450.95,8313.11
SSEL0: J2.47 U1.E9 | length 1157.1
  TOP w5.5: U1.E9@15267.73,9124.75 v1(15283.48,9140.5)
  BOTTOM w5.5: J2.47@14750.95,9849.95 J2.47@14750.95,9848.54 14831.5,9768 15138,9768 15314,9592 15314,9171.02 v1(15283.48,9140.5)
SSEL1: J2.75 U1.B11 | length 953.8
  TOP w5.5: U1.B11@15362.22,9061.76 15377.97,9077.5 v1(15472.46,9077.5)
  BOTTOM w5.5: J2.75@15450.95,9848.54 15523,9776.5 15523,9102 15514.5,9093.5 15488.46,9093.5 v1(15472.46,9077.5)
TCK: J1.72 U1.H14 | length 732.2
  TOP w5.5: U1.H14@15173.24,8967.27 v1(15188.99,8951.52)
  BOTTOM w5.5: v1(15188.99,8951.52) 15205,8935.51 15205,8878 15214,8869 15299,8869 15377,8791 15377,8437 15350.95,8410.95 15350.95,8380.05
TDI: J1.67 U1.J16 | length 736.9
  TOP w5.5: U1.J16@15141.75,8904.28 v1(15157.5,8888.53)
  BOTTOM w5.5: v1(15157.5,8888.53) 15157.5,8854.5 15185,8827 15273,8827 15310,8790 15310,8454 15276,8420 15276,8338.16 J1.67@15250.95,8313.11
TDO: J1.68 U1.J15 | length 722.6
  TOP w5.5: U1.J15@15141.75,8935.77 v1(15157.5,8920.02)
  BOTTOM w5.5: v1(15157.5,8920.02) 15136,8898.53 15136,8852 15175,8813 15261,8813 15295,8779 15295,8465 15250.95,8420.95 J1.68@15250.95,8363.11
TMS: J1.63 U1.G18 | length 571.1
  TOP w5.5: U1.G18@15204.74,8841.28 15204.74,8778.29 v1(15220.49,8762.54)
  BOTTOM w5.5: J1.63@15157,8319.16 15177,8339.16 15177,8438 15240,8501 15240,8726 15220.49,8745.51 v1(15220.49,8762.54)
U1_RX: J1.39 U1.K15 | length 1033
  TOP w5.5: v1(15094.5,8920.02) U1.K15@15110.25,8935.77
  BOTTOM w5.5: J1.39@14550.95,8313.11 14577,8339.16 14577,8524 14587.08,8534.08 14587.08,8672.92 14663.17,8749 14968.17,8749 15079,8859.83 15079,8904.52 v1(15094.5,8920.02)
U1_TX: J1.42 U1.K16 | length 930.8
  TOP w5.5: v1(15094.5,8888.53) U1.K16@15110.25,8904.28
  BOTTOM w5.5: J1.42@14600.95,8363.11 14603,8365.16 14603,8666.91 14670.09,8734 14975.09,8734 15094.5,8853.41 v1(15094.5,8888.53)
U2_RX: J1.57 U1.K18 | length 607.4
  TOP w5.5: v1(15094.5,8762.54) 15110.25,8778.29 U1.K18@15110.25,8841.28
  BOTTOM w5.5: J1.57@15000.95,8313.11 15026,8338.16 15026,8427 15135.5,8536.5 15135.5,8690.17 15094.5,8731.17 v1(15094.5,8762.54)
U2_TX: J1.60 U1.K17 | length 581
  TOP w5.5: v1(15094.5,8794.04) 15094.5,8857.03 U1.K17@15110.25,8872.78
  BOTTOM w5.5: J1.60@15050.95,8363.11 15050.95,8430.95 15151,8531 15151,8698 15111,8738 15111,8777.54 v1(15094.5,8794.04)
U3_RX: J1.70 U1.J14 | length 753
  TOP w5.5: U1.J14@15141.75,8967.27 v1(15157.5,8951.52)
  BOTTOM w5.5: v1(15157.5,8951.52) 15173,8936.02 15173,8865 15197,8841 15279,8841 15343,8777 15343,8455 15300.95,8412.95 J1.70@15300.95,8363.11
U3_TX: J1.62 U1.J17 | length 565.5
  TOP w5.5: U1.J17@15141.75,8872.78 15157.5,8857.03 v1(15157.5,8794.04)
  BOTTOM w5.5: J1.62@15100.95,8363.11 15100.95,8437.95 15188.75,8525.75 15188.75,8715.25 15173,8731 15173,8778.54 v1(15157.5,8794.04)
U4_TX: J2.82 U1.A13 | length 1088.5
  TOP w5.5: U1.A13@15393.72,8998.76 15488.21,8998.76 v1(15503.95,9014.51)
  BOTTOM w5.5: v1(15503.95,9014.51) 15547.22,9014.51 15601.99,9069.28 15601.99,9794.99 15626,9819 15626,9876 15603.46,9898.54 J2.82@15600.95,9898.54
U5_RX: J1.66 U1.F18 | length 494.5
  TOP w5.5: U1.F18@15236.24,8841.28 15236.24,8778.29 v1(15251.98,8762.54)
  BOTTOM w5.5: 15200.95,8381.05 15200.95,8441.95 15260,8501 15260,8732 15251.98,8740.02 v1(15251.98,8762.54)
U5_TX: J1.69 U1.H15 | length 774.5
  TOP w5.5: U1.H15@15173.24,8935.77 v1(15188.99,8920.02)
  BOTTOM w5.5: v1(15188.99,8920.02) 15188.99,8873.01 15208,8854 15292,8854 15361,8785 15361,8451 15326,8416 15326,8338.16 J1.69@15300.95,8313.11
U6_RX: J1.65 U1.F17 | length 599.7
  TOP w5.5: U1.F17@15236.24,8872.78 15251.98,8857.03 v1(15251.98,8794.04)
  BOTTOM w5.5: J1.65@15206.84,8319 15226,8338.16 15226,8434 15277,8485 15277,8730 15272,8735 15272,8774.02 v1(15251.98,8794.04)
U6_TX: J1.71 U1.G16 | length 734.2
  TOP w5.5: U1.G16@15204.74,8904.28 v1(15220.49,8888.53)
  BOTTOM w5.5: v1(15220.49,8888.53) 15300.47,8888.53 15394,8795 15394,8420 15376,8402 15376,8338.16 J1.71@15350.95,8313.11
pads on no net: U1.A4 U1.A6 U1.A7 U1.A8 U1.B4 U1.B5 U1.B7 U1.B8 U1.B15 U1.B17 U1.C1 U1.C2 U1.C4 U1.C5 U1.C6 U1.C7 U1.C8 U1.C11 U1.C17 U1.C18 U1.D1 U1.D2 U1.D5 U1.D6 U1.D7 U1.D8 U1.D9 U1.D11 U1.D14 U1.D15 U1.D16 U1.D17 U1.D18 U1.E1 U1.E2 U1.E3 U1.E5 U1.E6 U1.E7 U1.E8 U1.E10 U1.E12 U1.E14 U1.E15 U1.E16 U1.E17 U1.E18 U1.F1 U1.F2 U1.F3 U1.F14 U1.F15 U1.F16 U1.G1 U1.G2 U1.G3 U1.G14 U1.G15 U1.G17 U1.H2 U1.H3 U1.H4 U1.H16 U1.J1 U1.J2 U1.J3 U1.J4 U1.L2 U1.M15 U1.M16 U1.N17 U1.N18 U1.P5 U1.P12 U1.R9 U1.R10 U1.R12 U1.R13 U1.T1 U1.T3 U1.T9 U1.T10 U1.T11 U1.T13 U1.T14 U1.U2 U1.U9 U1.U10 U1.U11 U1.U12 U1.U14 U1.U15 U1.U16 U1.U17 U1.V8 U1.V9 U1.V10 U1.V11 U1.V12 U1.V13 U1.V14 U1.V15 U1.V16 U16.40 U20.10 U20.13 U20.15 Y1.3 Y1.4 Y2.3 Y2.4

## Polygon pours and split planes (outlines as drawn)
GND on TOP "TOP-No Net" (hatched 90Degree grid 4 track 5, remove dead copper, pour order 1003): 15233,8658 15093,8658 15093,8479 15233,8479
GND on TOP "TOP-No Net" (hatched 90Degree grid 4 track 5, remove dead copper, pour order 1002): 15500,8651 15602,8651 15602,8578 15634,8578 15634,8506 15584,8506 15584,8424 15410,8424 15410,8532 15500,8532
DP3V3 on TOP "TOP-No Net" (hatched 90Degree grid 4 track 5, remove dead copper, pour order 1001): 15623,8496 15745,8496 15745,8302 15596,8302 15596,8399 15623,8399
DP1V2_PLL on TOP "TOP-No Net" (hatched 90Degree grid 4 track 5, remove dead copper, pour order 1000): 15271,8696 15319,8744 15450,8744 15450,8550 15404,8550 15404,8511 15271,8511
DP1V2 on TOP "TOP-No Net" (hatched 90Degree grid 4 track 5, remove dead copper, pour order 1007): 15619,9179 15619,9535 15730,9535 15730,9339 15782,9339 15782,9179
DP1V2 on TOP "TOP-No Net" (hatched 90Degree grid 4 track 5, remove dead copper, pour order 1004): 15491,8725 15491,8796 15552,8796 15552,8725
GND on TOP "TOP-No Net" (hatched 90Degree grid 4 track 5, remove dead copper, pour order 1003): 15769,9472 15915,9472 15915,9423 15915,9264 15871,9264 15842,9264 15842,9337 15842,9356 15788,9356 15769,9356 15769,9472
NetL1_1 on TOP "TOP-No Net" (hatched 90Degree grid 4 track 5, remove dead copper, pour order 1002): 15744,9008 15691,9008 15691,9077 15691,9124 15731,9124 15747,9124 15747,9044 15747,9008 15744,9008
GND on TOP "TOP-No Net" (hatched 90Degree grid 4 track 5, remove dead copper, pour order 1001): 15790,8854 15898,8854 15898,8828 15898,8634 15866,8634 15820,8634 15820,8715 15820,8797.12 15798,8797.12 15790,8797.12 15790,8854
DP3V3 on TOP "TOP-No Net" (hatched 90Degree grid 4 track 5, remove dead copper, pour order 1000): 15790,8632 15648,8632 15648,8775 15648,8956 15733,8956 15754,8956 15754,8827 15754,8768 15767,8768 15790,8768 15790,8632
GND on TOP "TOP-No Net" (hatched 90Degree grid 4 track 5, remove dead copper, pour order 1000): 13303,9991.65 15998.91,9991.65 15998.91,9777 15998.91,8220 15447,8220 13243,8220 13243,9274 13243,9991.65 13302,9991.65
GND on BOTTOM "TOP-No Net" (hatched 90Degree grid 4 track 5, remove dead copper, pour order 1001): 13303,9991.65 15998.91,9991.65 15998.91,9777 15998.91,8220 15447,8220 13243,8220 13243,9274 13243,9991.65 13302,9991.65
GND on GND02 (split plane): 15963.31,9971.27 15966.95,9970.17 15970.29,9968.38 15973.23,9965.98 15975.64,9963.04 15977.42,9959.69 15978.53,9956.06 15978.85,9952.74 15978.81,9952.28 15978.81,8259.37 15978.85,8258.91 15978.53,8255.59 15977.42,8251.96 15975.64,8248.61 15973.23,8245.68 15970.29,8243.27 15966.95,8241.48 15963.31,8240.38 15959.99,8240.05 15959.54,8240.1 13282.37,8240.1 13281.91,8240.05 13278.59,8240.38 13274.96,8241.48 13271.61,8243.27 13268.68,8245.68 13266.27,8248.61 13264.48,8251.96 13263.38,8255.59 13263.05,8258.91 13263.1,8259.37 13263.1,9952.28 13263.05,9952.74 13263.38,9956.06 13264.48,9959.69 13266.27,9963.04 13268.68,9965.98 13271.61,9968.38 13274.96,9970.17 13278.59,9971.27 13281.91,9971.6 13282.37,9971.56 15959.54,9971.56 15959.99,9971.6
DP3V3 on PWR03 (split plane): 15884.77,9874.75 15938.81,9874.75 15938.81,8334.13 15882,8334.13 15882,8280.09 15689,8280.09 15689,8395 15573,8395 15573,8280.09 13357.13,8280.09 13357.13,8336.91 13303.09,8336.91 13303.09,9877.52 13359.91,9877.52 13359.91,9931.56 15884.77,9931.56
DP1V2 on PWR03 (split plane): 15749.9,9268.11 15631.13,9149.34 15630.02,9147.68 15629.63,9145.73 15629.63,8766.84 15577.89,8715.1 15528.11,8715.1 15461.1,8782.11 15461.1,8902 15460.71,8903.95 15459.6,8905.6 15429.6,8935.6 15362.84,9002.37 15361.19,9003.47 15359.24,9003.86 15141.75,9003.86 15139.8,9003.47 15138.14,9002.37 15108.14,8972.37 15020.86,8972.37 15020.86,9190.65 15044.35,9214.14 15231.14,9214.14 15231.14,9133.76 15231.53,9131.81 15232.63,9130.16 15244.4,9118.4 15246.05,9117.29 15248,9116.9 15364,9116.9 15365.95,9117.29 15367.6,9118.4 15585.6,9336.4 15586.71,9338.05 15587.1,9340 15587.1,9569.9 15749.9,9569.9
DP1V2_PLL on PWR03 (split plane): 15105.15,8844.75 15105.54,8842.8 15106.65,8841.14 15130.4,8817.4 15132.05,8816.29 15134,8815.9 15259.89,8815.9 15370.9,8704.89 15370.9,8525.11 15361.89,8516.1 15273.11,8516.1 15260.1,8529.11 15260.1,8652 15259.71,8653.95 15258.6,8655.6 15215.6,8698.6 15213.95,8699.71 15212,8700.1 14982.11,8700.1 14910.63,8771.58 14910.63,8930.42 14942.38,8962.17 15105.15,8962.17

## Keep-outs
Keep-Out Layer:
  the board outline again, w5

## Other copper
TOP:
  rectangle net GND: 15840,9288 15904,9389
  rectangle net DP1V2: 15720,9229 15776,9314
  rectangle net DP1V2: 15686,9261 15743,9330
  rectangle net GND: 15834,8660 15896,8797.81
  pour cut-out: 13990,9812 14144,9812 14144,9663 13990,9663
  pour cut-out: 13535.75,9712 13658.25,9712 13658.25,9634 13535.75,9634
  pour cut-out: 13438,9028 13475,9028 13475,9056 13553.79,9056 13553.79,8811 13438,8811
  pour cut-out: 13820,9582.19 13899.05,9582.19 13899.05,9490 13819.54,9490 13819.54,9581.9
  pour cut-out: 14536,9254 14536,9001 14381.33,9001 14381.33,8890.75 14209,8890.75 14209,9254
  pour cut-out: 13837.25,8702 13837.25,8593.7 13780,8593.7 13780,8702
  pour cut-out: 14351.3,8506 14351.3,8449 14197,8449 14197,8506
  pour cut-out: 14672,8609 14835,8609 14835,8522.48 14672,8522.48
  pour cut-out: 14740,8719 14816,8719 14816,8633.4 14697,8633.4 14697,8716.9 14738.9,8716.9
  pour cut-out: 15086,8836 15166,8836 15166,8762.55 15086,8762.55
  pour cut-out: 14941.54,8686 15056,8686 15056,8630 15092,8630 15092,8522.48 14928,8522.48 14928,8658 14941.54,8658
  text "TOP" at 13274,10209 h100
BOTTOM:
  pour cut-out: 15442,9672 15539,9672 15539,9566 15442,9566
  pour cut-out: 15232,9870 15375,9870 15375,9753 15232,9753
  pour cut-out: 15398,8991 15488,8991 15488,8851.91 15398,8851.91
  pour cut-out: 14952,8833 15189,8833 15189,8731.05 14954,8731.05 14954,8827
  pour cut-out: 14936,8903.99 15009,8903.99 15009,8858.19 14935.46,8858.19 14935.46,8903.95
  pour cut-out: 13849.7,9343 14817,9343 14817,9099 14388,8670 14016,8670 13737,8949 13737,9600 14110,9600 14110,9448 13849.7,9448
  text "BOTTOM" at 14682,10218 h100
GND02 (plane layer: these items are gaps in the copper):
  text "GND02" at 13594,10209 h100
PWR03 (plane layer: these items are gaps in the copper):
  region: 13275,8336.91 13275,8252.91 13357.13,8252.91 13357.13,8336.91
  region: 13359.91,9959.65 13275.91,9959.65 13275.91,9877.52 13359.91,9877.52
  region: 15966.91,9874.75 15966.91,9958.75 15884.77,9958.75 15884.77,9874.75
  rectangle: 15882,8252 15966,8334.13
  pour cut-out: 15689,8395 15689,8264 15573,8264 15573,8395
  lines w10: 15015.76,8967.27 14940.27,8967.27 14905.53,8932.53 14905.53,8769.47 14980,8695 15212,8695 15255,8652 15255,8527 15271,8511 15364,8511 15376,8523 15376,8707 15262,8821 15134,8821 15110.25,8844.75 15110.25,8967.27 ; 15015.76,8967.27 15110.25,8967.27 ; 15015.76,8967.27 15015.76,9192.76 15042.24,9219.24 15236.24,9219.24 15236.24,9133.76 15248,9122 15364,9122 15582,9340 15582,9575 15755,9575 15755,9266 15634.73,9145.73 15634.73,8764.73 15580,8710 15526,8710 15456,8780 15456,8902 15426,8932 15359.24,8998.76 15141.75,8998.76 15110.25,8967.27
  text "PWR03" at 14134,10212 h100

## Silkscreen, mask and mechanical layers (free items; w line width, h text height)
Top Overlay:
  lines w5: 14865,8629 14865,8665 ; 14902,8628 14902,8665
  text "Main_CORE V1.0" at 14814,9494 h100
Bottom Overlay:
  circle w7.87: c14625,9295 r56.36
  circle w7.87: c14035,9285 r56.36
  lines w5: 14505,8809 14505,9368 ; 14505,8809 13937,8809 13937,9368 14006,9368 14505,9368 ; 14505,8809 15347,8809 15347,9368 14505,9368
  text "A" at 14608,9281 h45
  text "A" at 14018,9271 h45
Drill Drawing:
  drawing of 2106 lines, arcs and shapes, not listed
  text "Purchase   Order &  Specification   Sheet" at 18193.43,14895.43 h77.51
  text "1.6" at 19725.9,14776.54 h38.75
  text "4" at 20984.87,14775.07 h38.75
  text "Dielectric Material:" at 17304.62,14769.67 h38.75
  text "IT180A" at 18311.68,14766.3 h38.75
  text "Board Thickness(MM):" at 18803.15,14766.26 h38.75
  text "Layers:" at 20183.47,14766.26 h38.75
  text "Osp" at 21099.61,14565.86 h38.75
  text "Surface Finished:" at 17306.18,14562.99 h38.75
  text "Gold Finger" at 20374.04,14563.31 h38.75
  text "Flash Gold" at 18977.77,14561.87 h38.75
  text "Hasl" at 18297.03,14560.91 h38.75
  text "Immersion Gold" at 19598.42,14559.96 h38.75
  text "Hasl Lead Free" at 18295.43,14421.83 h38.75
  text "Immersion Tin" at 18974.62,14415.02 h38.75
  text "Immersion Silver" at 19598.86,14414.4 h38.75
  text "Other" at 20378.12,14413.11 h38.75
  text "Angle" at 18665.08,14272.2 h38.75
  text "No" at 21099.73,14269.84 h38.75
  text "Yes" at 18307.2,14269.26 h38.75
  text "30" at 19643.04,14269.05 h38.75
  text "45" at 20404.46,14269.05 h38.75
  text "20" at 19004.85,14267.87 h38.75
  text "Finger Chamfer:" at 17308.6,14261.33 h38.75
  text "Matte Green" at 19589.08,14121.66 h38.75
  text "Blue" at 19011.81,14117.05 h38.75
  text "Other" at 20394.49,14114.68 h38.75
  text "Green" at 18307.66,14112.09 h38.75
  text "Soldermask Colours:" at 17304.94,14109 h38.75
  text "Black" at 19627.17,13969.8 h38.75
  text "Other" at 20398.43,13968.62 h38.75
  text "Silk Screen Colours:" at 17303.42,13965.02 h38.75
  text "White" at 18307.66,13963.27 h38.75
  text "Yellow" at 19008.66,13961.93 h38.75
  text "Spell Mode:" at 17297.63,13781.9 h38.75
  text "Open Windows:" at 19483.07,13779.64 h38.75
  text "None" at 20023.63,13778.07 h38.75
  text "V-cut" at 20007.48,13622.56 h38.75
  text "Stamp Hole" at 20979.14,13620.59 h38.75
  text "Bridge" at 18978.94,13615.62 h38.75
  text "Outline Profile:" at 17301.17,13615.36 h38.75
  text "Router" at 18327.95,13611.14 h38.75
  text "Gjb362A-96" at 20006.3,13474.92 h38.75
  text "Other" at 20981.89,13474.13 h38.75
  text "IPCII" at 18335.43,13472.56 h38.75
  text "IPCIII" at 18976.46,13471.88 h38.75
  text "Inspectionstandard:" at 17297.74,13469.63 h38.75
  text "Yes" at 18335.43,13321.38 h38.75
  text "No" at 18981.7,13320.74 h38.75
  text "Compare With IPC File" at 17298.13,13313.47 h38.75
  text "Not Appear" at 20977.17,13172.95 h38.75
  text "Specified Position" at 18971.09,13171.7 h38.75
  text "Required" at 18331.5,13164.68 h38.75
  text "Only Date Code" at 20011.42,13165.08 h38.75
  text "Fast Print Logo:" at 17301.82,13161.7 h38.75
  text "All via (<=0.5mm) must be filled(except open soldermask via)" at 18298.81,13014.63 h38.75
  text "By gerber" at 20972.05,13013.5 h38.75
  text "Via  Technic:" at 17306.12,13003.88 h38.75
  text "(unit:mil)MIN.track :                    MIN.spacing :                 MIN.hole:" at 17301.4,12857.03 h38.75
  text "6mil" at 18047.51,12853.29 h38.75
  text "5mil" at 19340.02,12852.02 h38.75
  text "12mil/22mil" at 20364.02,12849.02 h38.75
  text "Pressfit holes: The tolerance of                 is+/-0.05mm" at 18790.69,12711.14 h38.75
  text "*" at 20138.4,12708.83 h38.75
  text "Bow and Twist Tolerance:<=0.75%" at 17298.19,12708.04 h38.75
  text "1.  STACKING (dielectric thickness can be adjusted beween +/-2mil,but don,t less than 3.5mil; if inspection is Gjb362A" at 17395.4,12459.6 h32.81
  text "than don,t less than 4mil.)" at 17395.4,12359.6 h32.81
  text "2.  Control Impedance (track width can be adjusted +/-0.5mil , but don,t less than 4mil.)" at 17395.4,12259.6 h32.81
  text "高端、高速PCB设计文件与你共分享 PCB联盟网 www.pcbbar.com  QQ群:374116257" at 10050,10789 h196.85
  text "TOP" at 20912.26,10637.41 h39.27
  text "Hoz+Plating" at 20378.31,10635.62 h38.75
  text ".Legend" at 13286,10536 h30
  text "3.63" at 17541.98,10526.78 h39.27
  text "mil" at 17706.36,10526.56 h38.75
  text "pp(3313)" at 18430.77,10526.56 h39.27
  text "1oz" at 20411.46,10419.25 h39.27
  text "GND02" at 20912.26,10417.72 h39.27
  text "48.44" at 17489.62,10307.09 h39.27
  text "mil" at 17706.36,10306.88 h38.75
  text "Core" at 18430.77,10306.88 h39.27
  text "1oz" at 20411.46,10199.57 h39.27
  text "PWR03" at 20912.26,10198.03 h39.27
  text "pp(3313)" at 18404.77,10088.56 h39.27
  text "3.63" at 17541.98,10087.41 h39.27
  text "mil" at 17706.36,10087.19 h38.75
  text "BOTTOM" at 20912.26,9978.35 h39.27
  text "Hoz+Plating" at 20377.31,9972.39 h38.75
  text "ref layer" at 20320.42,9454.06 h32.81
  text "+/-10%" at 19639.3,9336.84 h38.75
  text "L1/4" at 17731.85,9330.93 h39.27
  text "5.5" at 18387.21,9330.57 h39.27
  text "L2/L3" at 20291.63,9329.79 h39.27
  text "50" at 19032.12,9327.42 h39.27
  text "ref layer" at 20342.62,8803.18 h32.81
  text "L1/4" at 17826.85,8685.93 h39.27
  text "+/-10%" at 19631.3,8684.84 h38.75
  text "4.1/8.5" at 18379.21,8678.57 h39.27
  text "L2/L3" at 20283.63,8677.79 h39.27
  text "100" at 19024.12,8675.42 h39.27
  text "Note:If etch layer don't have  above impedance track pls ignore" at 17691.02,8432.02 h51.67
